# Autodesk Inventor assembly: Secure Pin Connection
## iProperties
Created: 2011-05
Part Number: Secure Pin Connection
Document SubType Name: Assembly
Designer: 904Chiaki
ClientObjectVersion: 1
Author: 904Chiaki
